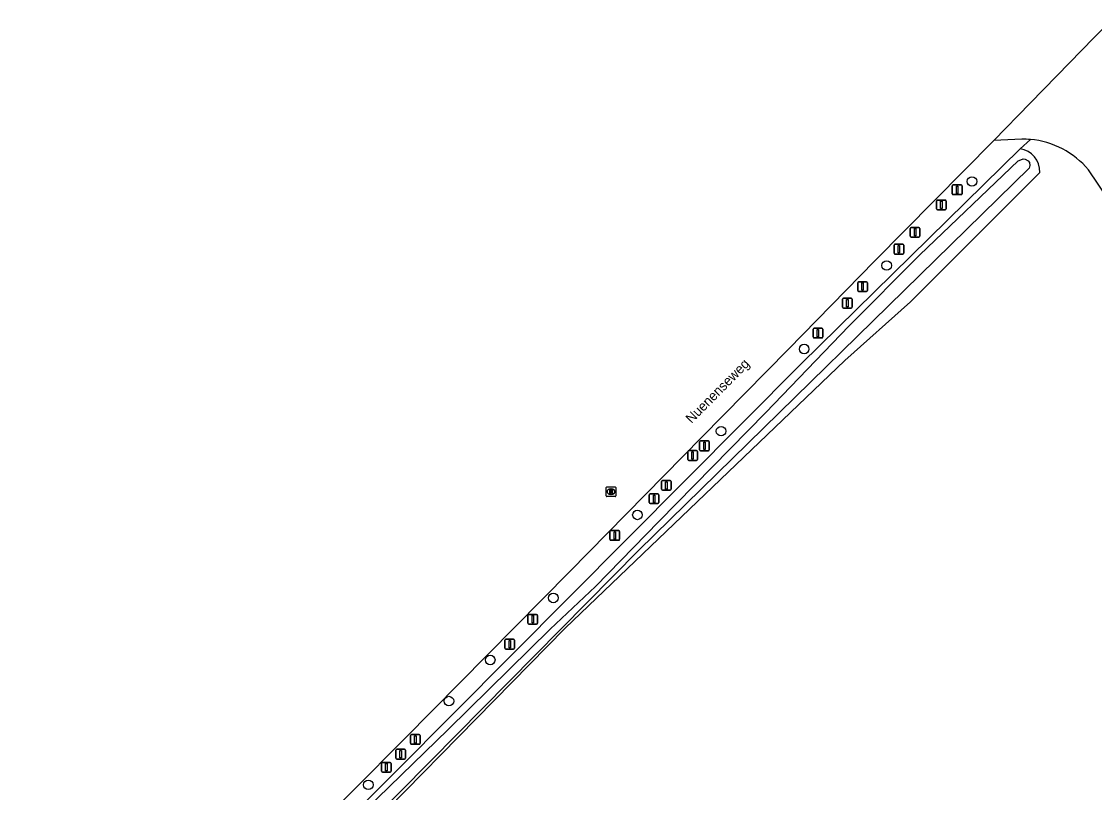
# Model space of a CAD drawing. Extents: x 162791 to 163827, y 385795 to 386523.
# Drawn here: x 163033.3 to 163143.1, y 386358.7 to 386437.6 of the extents above; entities that cross this region are included whole.
import ezdxf

# ---------------------------------------------------------------- set-up
doc = ezdxf.new("R2010")
doc.units = 0
for name, color, linetype in [('IMGEO_Afsluitpaal', 7, 'Continuous'), ('IMGEO_Boom', 7, 'Continuous'), ('IMGEO_Erf', 7, 'Continuous'), ('IMGEO_Groenvoorziening', 7, 'Continuous'), ('IMGEO_Openbare_ruimte_label', 7, 'Continuous'), ('IMGEO_Rijbaan_lokaal_open', 7, 'Continuous'), ('IMGEO_Rioolput', 7, 'Continuous'), ('IMGEO_Waterloop', 7, 'Continuous'), ('IMGEO_Woonerf_open', 7, 'Continuous')]:
    doc.layers.add(name, color=color, linetype=linetype)

msp = doc.modelspace()

# ---------------------------------------------------------------- linework, layer by layer
at = {"layer": 'IMGEO_Afsluitpaal'}
for p, q in [((163128.56, 386419.97), (163128.56, 386420.77)), ((163128.56, 386420.77), (163128.56, 386419.97)), ((163128.66, 386420.87), (163129.45, 386420.87)), ((163129.45, 386420.87), (163128.66, 386420.87)), ((163129.55, 386420.77), (163129.55, 386419.97)), ((163129.55, 386419.97), (163129.55, 386420.77)), ((163129.45, 386419.87), (163128.66, 386419.87)), ((163128.66, 386419.87), (163129.45, 386419.87)), ((163126.94, 386418.42), (163126.94, 386419.22)), ((163126.94, 386419.22), (163126.94, 386418.42)), ((163127.04, 386419.32), (163127.83, 386419.32)), ((163127.83, 386419.32), (163127.04, 386419.32)), ((163127.83, 386418.32), (163127.04, 386418.32)), ((163127.04, 386418.32), (163127.83, 386418.32)), ((163127.93, 386419.22), (163127.93, 386418.42)), ((163127.93, 386418.42), (163127.93, 386419.22)), ((163124.25, 386415.62), (163124.25, 386416.42)), ((163124.25, 386416.42), (163124.25, 386415.62)), ((163124.35, 386416.52), (163125.14, 386416.52)), ((163125.14, 386416.52), (163124.35, 386416.52)), ((163125.24, 386416.42), (163125.24, 386415.62)), ((163125.24, 386415.62), (163125.24, 386416.42)), ((163125.14, 386415.52), (163124.35, 386415.52)), ((163124.35, 386415.52), (163125.14, 386415.52)), ((163122.59, 386413.89), (163122.59, 386414.69)), ((163122.59, 386414.69), (163122.59, 386413.89)), ((163122.69, 386414.79), (163123.48, 386414.79)), ((163123.48, 386414.79), (163122.69, 386414.79)), ((163123.58, 386414.69), (163123.58, 386413.89)), ((163123.58, 386413.89), (163123.58, 386414.69)), ((163123.48, 386413.79), (163122.69, 386413.79)), ((163122.69, 386413.79), (163123.48, 386413.79)), ((163118.87, 386410.05), (163118.87, 386410.85)), ((163118.87, 386410.85), (163118.87, 386410.05)), ((163118.97, 386410.95), (163119.76, 386410.95)), ((163119.76, 386410.95), (163118.97, 386410.95)), ((163119.86, 386410.85), (163119.86, 386410.05)), ((163119.86, 386410.05), (163119.86, 386410.85)), ((163119.76, 386409.95), (163118.97, 386409.95)), ((163118.97, 386409.95), (163119.76, 386409.95)), ((163117.32, 386408.36), (163117.32, 386409.16)), ((163117.32, 386409.16), (163117.32, 386408.36)), ((163117.42, 386409.26), (163118.21, 386409.26)), ((163118.21, 386409.26), (163117.42, 386409.26)), ((163118.31, 386409.16), (163118.31, 386408.36)), ((163118.31, 386408.36), (163118.31, 386409.16)), ((163118.21, 386408.26), (163117.42, 386408.26)), ((163117.42, 386408.26), (163118.21, 386408.26)), ((163114.4, 386406.2), (163115.19, 386406.2)), ((163115.19, 386406.2), (163114.4, 386406.2)), ((163114.3, 386405.3), (163114.3, 386406.1)), ((163114.3, 386406.1), (163114.3, 386405.3)), ((163115.19, 386405.2), (163114.4, 386405.2)), ((163114.4, 386405.2), (163115.19, 386405.2)), ((163115.29, 386406.1), (163115.29, 386405.3)), ((163115.29, 386405.3), (163115.29, 386406.1)), ((163102.69, 386393.76), (163102.69, 386394.56)), ((163102.69, 386394.56), (163102.69, 386393.76)), ((163102.79, 386394.66), (163103.58, 386394.66)), ((163103.58, 386394.66), (163102.79, 386394.66)), ((163103.68, 386394.56), (163103.68, 386393.76)), ((163103.68, 386393.76), (163103.68, 386394.56)), ((163101.47, 386392.77), (163101.47, 386393.57)), ((163101.47, 386393.57), (163101.47, 386392.77)), ((163101.57, 386393.67), (163102.36, 386393.67)), ((163102.36, 386393.67), (163101.57, 386393.67)), ((163102.46, 386393.57), (163102.46, 386392.77)), ((163102.46, 386392.77), (163102.46, 386393.57)), ((163103.58, 386393.66), (163102.79, 386393.66)), ((163102.79, 386393.66), (163103.58, 386393.66)), ((163102.36, 386392.67), (163101.57, 386392.67)), ((163101.57, 386392.67), (163102.36, 386392.67)), ((163098.78, 386389.71), (163098.78, 386390.51)), ((163098.78, 386390.51), (163098.78, 386389.71)), ((163098.88, 386390.61), (163099.67, 386390.61)), ((163099.67, 386390.61), (163098.88, 386390.61)), ((163099.77, 386390.51), (163099.77, 386389.71)), ((163099.77, 386389.71), (163099.77, 386390.51)), ((163097.53, 386388.35), (163097.53, 386389.15)), ((163097.53, 386389.15), (163097.53, 386388.35)), ((163097.63, 386389.25), (163098.42, 386389.25)), ((163098.42, 386389.25), (163097.63, 386389.25)), ((163098.52, 386389.15), (163098.52, 386388.35)), ((163098.52, 386388.35), (163098.52, 386389.15)), ((163099.67, 386389.61), (163098.88, 386389.61)), ((163098.88, 386389.61), (163099.67, 386389.61)), ((163098.42, 386388.25), (163097.63, 386388.25)), ((163097.63, 386388.25), (163098.42, 386388.25)), ((163093.51, 386384.59), (163093.51, 386385.39)), ((163093.51, 386385.39), (163093.51, 386384.59)), ((163093.61, 386385.49), (163094.4, 386385.49)), ((163094.4, 386385.49), (163093.61, 386385.49)), ((163094.5, 386385.39), (163094.5, 386384.59)), ((163094.5, 386384.59), (163094.5, 386385.39)), ((163094.4, 386384.49), (163093.61, 386384.49)), ((163093.61, 386384.49), (163094.4, 386384.49)), ((163085.11, 386376), (163085.11, 386376.8)), ((163085.11, 386376.8), (163085.11, 386376)), ((163085.21, 386376.9), (163086, 386376.9)), ((163086, 386376.9), (163085.21, 386376.9)), ((163086.1, 386376.8), (163086.1, 386376)), ((163086.1, 386376), (163086.1, 386376.8)), ((163086, 386375.9), (163085.21, 386375.9)), ((163085.21, 386375.9), (163086, 386375.9)), ((163082.85, 386374.36), (163083.64, 386374.36)), ((163083.64, 386374.36), (163082.85, 386374.36)), ((163082.75, 386373.46), (163082.75, 386374.26)), ((163082.75, 386374.26), (163082.75, 386373.46)), ((163083.64, 386373.36), (163082.85, 386373.36)), ((163082.85, 386373.36), (163083.64, 386373.36)), ((163083.74, 386374.26), (163083.74, 386373.46)), ((163083.74, 386373.46), (163083.74, 386374.26)), ((163073.08, 386363.71), (163073.08, 386364.51)), ((163073.08, 386364.51), (163073.08, 386363.71)), ((163073.18, 386364.61), (163073.97, 386364.61)), ((163073.97, 386364.61), (163073.18, 386364.61)), ((163074.07, 386364.51), (163074.07, 386363.71)), ((163074.07, 386363.71), (163074.07, 386364.51)), ((163073.97, 386363.61), (163073.18, 386363.61)), ((163073.18, 386363.61), (163073.97, 386363.61)), ((163071.58, 386362.2), (163071.58, 386363)), ((163071.58, 386363), (163071.58, 386362.2)), ((163071.68, 386363.1), (163072.47, 386363.1)), ((163072.47, 386363.1), (163071.68, 386363.1)), ((163072.57, 386363), (163072.57, 386362.2)), ((163072.57, 386362.2), (163072.57, 386363)), ((163070.11, 386360.85), (163070.11, 386361.65)), ((163070.11, 386361.65), (163070.11, 386360.85)), ((163070.21, 386361.75), (163071, 386361.75)), ((163071, 386361.75), (163070.21, 386361.75)), ((163071.1, 386361.65), (163071.1, 386360.85)), ((163071.1, 386360.85), (163071.1, 386361.65)), ((163072.47, 386362.1), (163071.68, 386362.1)), ((163071.68, 386362.1), (163072.47, 386362.1)), ((163071, 386360.75), (163070.21, 386360.75)), ((163070.21, 386360.75), (163071, 386360.75))]:
    msp.add_line(p, q, dxfattribs=at)
for points in [[(163128.98, 386420.74), (163129.13, 386420.74), (163129.13, 386419.99), (163128.98, 386419.99), (163128.98, 386420.74)], [(163127.36, 386419.2), (163127.51, 386419.2), (163127.51, 386418.45), (163127.36, 386418.45), (163127.36, 386419.2)], [(163124.67, 386416.39), (163124.82, 386416.39), (163124.82, 386415.64), (163124.67, 386415.64), (163124.67, 386416.39)], [(163123.01, 386414.66), (163123.16, 386414.66), (163123.16, 386413.91), (163123.01, 386413.91), (163123.01, 386414.66)], [(163119.29, 386410.83), (163119.44, 386410.83), (163119.44, 386410.08), (163119.29, 386410.08), (163119.29, 386410.83)], [(163117.74, 386409.13), (163117.89, 386409.13), (163117.89, 386408.38), (163117.74, 386408.38), (163117.74, 386409.13)], [(163114.72, 386406.07), (163114.87, 386406.07), (163114.87, 386405.32), (163114.72, 386405.32), (163114.72, 386406.07)], [(163103.11, 386394.54), (163103.26, 386394.54), (163103.26, 386393.79), (163103.11, 386393.79), (163103.11, 386394.54)], [(163101.89, 386393.54), (163102.04, 386393.54), (163102.04, 386392.79), (163101.89, 386392.79), (163101.89, 386393.54)], [(163099.2, 386390.48), (163099.35, 386390.48), (163099.35, 386389.73), (163099.2, 386389.73), (163099.2, 386390.48)], [(163097.95, 386389.12), (163098.1, 386389.12), (163098.1, 386388.37), (163097.95, 386388.37), (163097.95, 386389.12)], [(163093.93, 386385.36), (163094.08, 386385.36), (163094.08, 386384.61), (163093.93, 386384.61), (163093.93, 386385.36)], [(163085.53, 386376.78), (163085.68, 386376.78), (163085.68, 386376.03), (163085.53, 386376.03), (163085.53, 386376.78)], [(163083.17, 386374.23), (163083.32, 386374.23), (163083.32, 386373.48), (163083.17, 386373.48), (163083.17, 386374.23)], [(163073.5, 386364.48), (163073.65, 386364.48), (163073.65, 386363.73), (163073.5, 386363.73), (163073.5, 386364.48)], [(163072, 386362.97), (163072.15, 386362.97), (163072.15, 386362.22), (163072, 386362.22), (163072, 386362.97)], [(163070.53, 386361.63), (163070.68, 386361.63), (163070.68, 386360.88), (163070.53, 386360.88), (163070.53, 386361.63)]]:
    msp.add_lwpolyline(points, dxfattribs=at)
for centre, start, end in [((163128.66, 386420.77), 90, 180), ((163128.66, 386420.77), 90, 180), ((163129.45, 386420.77), 0, 90), ((163129.45, 386420.77), 360, 90), ((163128.66, 386419.97), 180, 270), ((163128.66, 386419.97), 180, 270), ((163129.45, 386419.97), 270, 0), ((163129.45, 386419.97), 270, 0), ((163127.04, 386419.22), 90, 180), ((163127.04, 386419.22), 90, 180), ((163127.04, 386418.42), 180, 270), ((163127.04, 386418.42), 180, 270), ((163127.83, 386419.22), 0, 90), ((163127.83, 386419.22), 360, 90), ((163127.83, 386418.42), 270, 0), ((163127.83, 386418.42), 270, 0), ((163124.35, 386416.42), 90, 180), ((163124.35, 386416.42), 90, 180), ((163125.14, 386416.42), 0, 90), ((163125.14, 386416.42), 360, 90), ((163124.35, 386415.62), 180, 270), ((163124.35, 386415.62), 180, 270), ((163125.14, 386415.62), 270, 0), ((163125.14, 386415.62), 270, 0), ((163122.69, 386414.69), 90, 180), ((163122.69, 386414.69), 90, 180), ((163122.69, 386413.89), 180, 270), ((163122.69, 386413.89), 180, 270), ((163123.48, 386414.69), 0, 90), ((163123.48, 386414.69), 360, 90), ((163123.48, 386413.89), 270, 0), ((163123.48, 386413.89), 270, 0), ((163118.97, 386410.85), 90, 180), ((163118.97, 386410.85), 90, 180), ((163119.76, 386410.85), 0, 90), ((163119.76, 386410.85), 360, 90), ((163118.97, 386410.05), 180, 270), ((163118.97, 386410.05), 180, 270), ((163119.76, 386410.05), 270, 0), ((163119.76, 386410.05), 270, 0), ((163117.42, 386409.16), 90, 180), ((163117.42, 386409.16), 90, 180), ((163118.21, 386409.16), 0, 90), ((163118.21, 386409.16), 360, 90), ((163117.42, 386408.36), 180, 270), ((163117.42, 386408.36), 180, 270), ((163118.21, 386408.36), 270, 0), ((163118.21, 386408.36), 270, 0), ((163114.4, 386406.1), 90, 180), ((163114.4, 386406.1), 90, 180), ((163115.19, 386406.1), 0, 90), ((163115.19, 386406.1), 360, 90), ((163114.4, 386405.3), 180, 270), ((163114.4, 386405.3), 180, 270), ((163115.19, 386405.3), 270, 0), ((163115.19, 386405.3), 270, 0), ((163102.79, 386394.56), 90, 180), ((163102.79, 386394.56), 90, 180), ((163103.58, 386394.56), 0, 90), ((163103.58, 386394.56), 360, 90), ((163101.57, 386393.57), 90, 180), ((163101.57, 386393.57), 90, 180), ((163102.36, 386393.57), 0, 90), ((163102.36, 386393.57), 360, 90), ((163102.79, 386393.76), 180, 270), ((163102.79, 386393.76), 180, 270), ((163103.58, 386393.76), 270, 0), ((163103.58, 386393.76), 270, 0), ((163101.57, 386392.77), 180, 270), ((163101.57, 386392.77), 180, 270), ((163102.36, 386392.77), 270, 0), ((163102.36, 386392.77), 270, 0), ((163098.88, 386390.51), 90, 180), ((163098.88, 386390.51), 90, 180), ((163099.67, 386390.51), 0, 90), ((163099.67, 386390.51), 360, 90), ((163097.63, 386389.15), 90, 180), ((163097.63, 386389.15), 90, 180), ((163098.42, 386389.15), 0, 90), ((163098.42, 386389.15), 360, 90), ((163098.88, 386389.71), 180, 270), ((163098.88, 386389.71), 180, 270), ((163099.67, 386389.71), 270, 0), ((163099.67, 386389.71), 270, 0), ((163097.63, 386388.35), 180, 270), ((163097.63, 386388.35), 180, 270), ((163098.42, 386388.35), 270, 0), ((163098.42, 386388.35), 270, 0), ((163093.61, 386385.39), 90, 180), ((163093.61, 386385.39), 90, 180), ((163094.4, 386385.39), 0, 90), ((163094.4, 386385.39), 360, 90), ((163093.61, 386384.59), 180, 270), ((163093.61, 386384.59), 180, 270), ((163094.4, 386384.59), 270, 0), ((163094.4, 386384.59), 270, 0), ((163085.21, 386376.8), 90, 180), ((163085.21, 386376.8), 90, 180), ((163086, 386376.8), 0, 90), ((163086, 386376.8), 360, 90), ((163085.21, 386376), 180, 270), ((163085.21, 386376), 180, 270), ((163086, 386376), 270, 0), ((163086, 386376), 270, 0), ((163082.85, 386374.26), 90, 180), ((163082.85, 386374.26), 90, 180), ((163083.64, 386374.26), 0, 90), ((163083.64, 386374.26), 360, 90), ((163082.85, 386373.46), 180, 270), ((163082.85, 386373.46), 180, 270), ((163083.64, 386373.46), 270, 0), ((163083.64, 386373.46), 270, 0), ((163073.18, 386364.51), 90, 180), ((163073.18, 386364.51), 90, 180), ((163073.97, 386364.51), 0, 90), ((163073.97, 386364.51), 360, 90), ((163073.18, 386363.71), 180, 270), ((163073.18, 386363.71), 180, 270), ((163073.97, 386363.71), 270, 0), ((163073.97, 386363.71), 270, 0), ((163071.68, 386363), 90, 180), ((163071.68, 386363), 90, 180), ((163072.47, 386363), 0, 90), ((163072.47, 386363), 360, 90), ((163070.21, 386361.65), 90, 180), ((163070.21, 386361.65), 90, 180), ((163071, 386361.65), 0, 90), ((163071, 386361.65), 360, 90), ((163071.68, 386362.2), 180, 270), ((163071.68, 386362.2), 180, 270), ((163072.47, 386362.2), 270, 0), ((163072.47, 386362.2), 270, 0), ((163070.21, 386360.85), 180, 270), ((163070.21, 386360.85), 180, 270), ((163071, 386360.85), 270, 0), ((163071, 386360.85), 270, 0)]:
    msp.add_arc(centre, 0.1, start, end, dxfattribs=at)
at = {"layer": 'IMGEO_Boom'}
for centre in [(163130.57, 386421.22), (163121.84, 386412.62), (163113.39, 386404.07), (163104.88, 386395.66), (163096.32, 386387.09), (163087.71, 386378.59), (163081.25, 386372.24), (163077.02, 386368.03), (163068.77, 386359.46)]:
    msp.add_circle(centre, 0.489, dxfattribs=at)
at = {"layer": 'IMGEO_Erf'}
msp.add_lwpolyline([(163137.51, 386422.15), (163124.27, 386408.89), (163117.54, 386402.88), (163088.92, 386375.51), (163061.65, 386347.74), (163037.47, 386323.98), (163037.35, 386323.86)], dxfattribs=at)
msp.add_arc((163135.15, 386422.23), 2.36, 358.039, 81.6094, dxfattribs=at)
at = {"layer": 'IMGEO_Groenvoorziening'}
for points in [[(163136.56, 386425.52), (163135.49, 386424.57)], [(163037.35, 386323.86), (163037.08, 386323.91), (163036.81, 386323.98), (163036.56, 386324.12), (163036.51, 386324.17), (163036.36, 386324.32), (163036.23, 386324.63), (163036.26, 386324.83), (163036.37, 386325.09), (163047.78, 386336.92), (163113.11, 386402.59), (163135.49, 386424.57)]]:
    msp.add_lwpolyline(points, dxfattribs=at)
at = {"layer": 'IMGEO_Rijbaan_lokaal_open'}
for points in [[(163132.8, 386425.42), (163136.54, 386429.25), (163139.27, 386432.04), (163143.08, 386435.96), (163144.71, 386437.6)], [(163033.25, 386324.39), (163061.91, 386353.55), (163072.52, 386364.21), (163089.39, 386381.29), (163102.91, 386395.06), (163111.75, 386404.01), (163120.64, 386413.08), (163132.8, 386425.42)]]:
    msp.add_lwpolyline(points, dxfattribs=at)
at = {"layer": 'IMGEO_Rioolput'}
for p, q in [((163093.11, 386389.04), (163093.11, 386389.9)), ((163093.18, 386389.97), (163094.04, 386389.97)), ((163093.6, 386389.75), (163093.62, 386389.75)), ((163094.11, 386389.9), (163094.11, 386389.04)), ((163094.04, 386388.97), (163093.18, 386388.97)), ((163093.62, 386389.19), (163093.6, 386389.19))]:
    msp.add_line(p, q, dxfattribs=at)
for points in [[(163093.11, 386389.04), (163093.11, 386389.9)], [(163093.18, 386389.97), (163094.04, 386389.97)], [(163094.11, 386389.9), (163094.11, 386389.04)], [(163094.04, 386388.97), (163093.18, 386388.97)], [(163093.7, 386389.67), (163093.45, 386389.67), (163093.45, 386389.27)], [(163093.45, 386389.27), (163093.57, 386389.27), (163093.57, 386389.43), (163093.58, 386389.43)], [(163093.63, 386389.59), (163093.57, 386389.59), (163093.57, 386389.51)], [(163093.57, 386389.51), (163093.62, 386389.51)], [(163093.63, 386389.4), (163093.7, 386389.27), (163093.84, 386389.27), (163093.77, 386389.4)]]:
    msp.add_lwpolyline(points, dxfattribs=at)
for centre, radius, start, end in [((163093.19, 386389.89), 0.0765, 91.552, 178.448), ((163093.19, 386389.89), 0.0765, 91.552, 178.448), ((163094.03, 386389.89), 0.0765, 1.552, 88.448), ((163094.03, 386389.89), 0.0765, 1.552, 88.448), ((163093.19, 386389.04), 0.0765, 181.552, 268.448), ((163093.19, 386389.04), 0.0765, 181.552, 268.448), ((163093.58, 386389.38), 0.0533, 26.0293, 88.6989), ((163093.61, 386389.7), 0.19, 274.7715, 282.9687), ((163093.63, 386389.49), 0.0964, 77.0061, 93.1865), ((163093.65, 386389.55), 0.0378, 276.6634, 79.6772), ((163093.7, 386389.56), 0.109, 350.3612, 89.416), ((163093.7, 386389.56), 0.112, 277.5842, 350.9817), ((163093.68, 386389.34), 0.108, 29.5134, 73.7905), ((163094.03, 386389.04), 0.0765, 271.552, 358.448), ((163094.03, 386389.04), 0.0765, 271.552, 358.448)]:
    msp.add_arc(centre, radius, start, end, dxfattribs=at)
for centre, major_axis, ratio, start_param, end_param in [((163093.6, 386389.47), (-0.387, 0.002), 0.722429, 4.712389, 7.853982), ((163093.62, 386389.47), (-0.39, 0.002), 0.717154, 1.570796, 4.712389)]:
    msp.add_ellipse(centre, major_axis=major_axis, ratio=ratio, start_param=start_param, end_param=end_param, dxfattribs=at)
at = {"layer": 'IMGEO_Waterloop'}
for points in [[(163135.3, 386423.33), (163135.56, 386423.45), (163135.82, 386423.52), (163136.02, 386423.51), (163136.32, 386423.34), (163136.46, 386423.15), (163136.49, 386422.86), (163136.43, 386422.59), (163096.46, 386383.48), (163075.17, 386361.92), (163055.68, 386342.23)], [(163063.71, 386352.26), (163076.93, 386365.13), (163087.4, 386375.4), (163092.04, 386379.77), (163098.52, 386386.4), (163109.47, 386397.58), (163117.95, 386406.42), (163125.22, 386413.72), (163135.3, 386423.33)]]:
    msp.add_lwpolyline(points, dxfattribs=at)
at = {"layer": 'IMGEO_Woonerf_open'}
for points in [[(163135.69, 386425.56), (163132.8, 386425.42)], [(163189.47, 386351.45), (163174.34, 386374.85), (163166.31, 386386.55), (163158.23, 386399.07), (163142.49, 386422.41)]]:
    msp.add_lwpolyline(points, dxfattribs=at)
for centre, radius, start, end in [((163135.72, 386416.51), 9.04, 84.6734, 90.1932), ((163135.73, 386416.71), 8.85, 40.1255, 84.6265)]:
    msp.add_arc(centre, radius, start, end, dxfattribs=at)

# ---------------------------------------------------------------- texts
at = {"layer": 'IMGEO_Openbare_ruimte_label'}
msp.add_text('Nuenenseweg', height=1, rotation=45.3242, dxfattribs=at).set_placement((163101.86, 386396.39))

doc.saveas('drawing.dxf')
